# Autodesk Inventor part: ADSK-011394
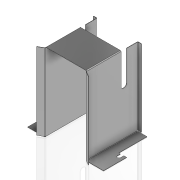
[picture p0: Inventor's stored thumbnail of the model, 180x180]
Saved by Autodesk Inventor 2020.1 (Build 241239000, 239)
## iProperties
Created: 2000-01
Part Number: ADSK-011394
Material: 1.0312 DC05
Document SubType Name: Tôlerie
Designer: glanglot
Density: 1 g/cm^3
Sheet Metal Rule: Stahlblech 1.0312 - DC05 -   1.5mm
Appearance: Chrom - poliert
Mass: 262.367 g
Surface Area: 3543.47 cm^2
Volume: 262.367 cm^3
Sheet Metal Width: 235,19077 mm
Sheet Metal Length: 887,57168 mm
Sheet Metal Area: 208748,66262 mm^2
Flat Pattern Width: 23.5191 cm
Flat Pattern Length: 88.7572 cm
Flat Pattern Area: 2087.49 cm^2
Control State: 0
Checked Out: False
Master: False
Shininess: 0.0
Length Units: 11269
Angle Units: 11279
Time Units: 11290
Mass Units: 11283
Length Display Precision: 5
Angle Display Precision: 5
Compacted: True
CUTLENGTH: 9.47 X 34.82 (330 SI)
MATERIAL DESC: SHEET,S/S, 16 GA
MATERIAL_NUMBER: A084639
G_L: 887,6x235,2 mm
Thickness: 1,50000 mm
Dimensions: 292x301,6x212,6 mm
Mass: 0,262 kg
Semi finished: Stahlblech 1.0312 - DC05 -   1.5mm
DocNumber: ADSK-011394.ipt
Folder: 01 - Themengebiete\Simplification\01 - Packaging machine\
VDS_Category: 3D Komponenten
Density: 0.0
Volumn: 0.0
Area: 0.0
PropertySet Name: Model Information
Author: glanglot
Revision Number: -
Title: Box
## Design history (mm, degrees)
node "Konturlasche1"
  sketch "Sketch1"
    geometry: L1 (0, 0)-(68, 0); L2 (68, 298.5)-(68, 0)
    constraints: 5 end point, 1 horizontal, 1 vertical
    dimensions: "d54" = 68 distance of L1.start L1.end; "d85" = 298.5 distance of L2.start L1.end
node "Lasche1"
sketch "Sketch5"
  geometry: L1 (66, 179.325)-(66, 295.325); L2 (44, 295.325)-(44, 179.325); L3 (66, 295.325)-(44, 295.325); L4 (0, 297.218)-(0, 293.825) reference; L5 (198.268, -0.175)-(0, -0.175) reference; L6 (0, 295.325)-(198.268, 295.325) reference; L7 (0, 295.325)-(0, -0.175) reference; A1 r 11 centre (55, 179.325) between (44, 179.325) and (66, 179.325)
  constraints: 6 end point, 4 point on circle, 2 point on line, 2 tangent, 1 centre point, 1 collinear, 1 parallel, 1 perpendicular
  dimensions: "d19" = 22 distance between parallel lines of L1 L2; "d86" = 116 distance from line of L6 A1.centre; "d87" = 44 distance between parallel lines of L7 L2
feature "Ausklinkung1" sketch "Sketch5" dims "d79" = 1.5 (= Thickness), "d80" = 0
sketch "Skizze12"
  geometry: L1 (0, 0)-(30, 0); L2 (30, 0)-(30, 111); L3 (30, 111)-(0, 111); L4 (0, 111)-(0, 0)
  constraints: 8 end point, 2 parallel, 1 horizontal, 1 perpendicular
  dimensions: "d81" = 30 distance of L3.end L2.end; "d82" = 111 distance of L2.end L1.end
feature "Ausklinkung2" sketch "Skizze12" dims "d83" = 1.5 (= Thickness), "d84" = 0
node "Lasche2"
feature "Ecke4" dims "d56" = 1.5 (= Thickness), "d98" = 6 (= CornerReliefSize), "d99" = 1.5 (= TransitionRadius), "d100" = 1.5 (= TailleJeu), "d101" = 0, "d102" = 10
workplane "Arbeitsebene3"
sketch "Sketch10"
  geometry: L1 (10.75, -76.464)-(10.75, -89.025); L2 (23.25, -76.464)-(23.25, -89.025); L3 (10.75, -89.025)-(23.25, -89.025); L4 (0, -89.025)-(30, -89.025) reference; L5 (63.973, -197.464)-(30, -197.464) reference; L6 (0, -89.025)-(0, -0.025) reference; L7 (146, 54.992)-(146, -242.627) reference; A1 r 6.25 centre (17, -76.464) between (23.25, -76.464) and (10.75, -76.464)
  constraints: 6 end point, 2 point on circle, 2 tangent, 2 vertical, 1 centre point, 1 collinear, 1 horizontal
  dimensions: "d103" = 121 distance from line of A1.centre L5; "d104" = 12.5 distance of L1.end L2.end; "d114" = 129 distance from line of L7 A1.centre
feature "Ausklinkung3" sketch "Sketch10" dims "d106" = 1.5 (= Thickness), "d107" = 0
node "Fillet7" dims "d53" = 3
node "Mirror1"
feature "Biegung4" dims "d56" = 1.5 (= Thickness), "d109" = 1.5 (= BendReliefWidth), "d110" = 0.75 (= BendReliefDepth), "d111" = 3 (= MinimumRemnant), "d112" = 1.5 (= TransitionRadius), "d113" = 1.5 (= BendRadius), "SeamGap" = 0.00508
node "Solide1"
node "Corps solides"
node "Corps surfaciques"
feature "Grobblech1" dims "d56" = 1.5 (= Thickness), "d57" = 1.5 (= BendReliefWidth), "d58" = 0.75 (= BendReliefDepth), "d59" = 3 (= MinimumRemnant), "d60" = 1.5 (= TransitionRadius), "d61" = 200, "d62" = 1.5 (= BendRadius), "d63" = 1.5, "d64" = 6 (= CornerReliefSize), "d65" = 1.5 (= TailleJeu), "d66" = 1.5 (= TailleRayonJacobi), "SeamGap" = 0.00508
node "Volumenkörper2"
feature "Biegung1" dims "d56" = 1.5 (= Thickness), "d57" = 1.5 (= BendReliefWidth), "d58" = 0.75 (= BendReliefDepth), "d59" = 3 (= MinimumRemnant), "d60" = 1.5 (= TransitionRadius), "d62" = 1.5 (= BendRadius), "d63" = 1.5, "SeamGap" = 0.00508
feature "Ecke1" dims "d63" = 1.5, "d64" = 6 (= CornerReliefSize), "d65" = 1.5 (= TailleJeu), "d66" = 1.5 (= TailleRayonJacobi)
sketch "Skizze11"
  geometry: L1 through (-147.75, 0) direction (1, -2.37e-17); L2 through (0, 12.5) direction (1.28e-16, 1); L3 (0, 25)-(-295.5, 25); L4 (-295.5, 25)-(-295.5, 0)
  constraints: 6 end point, 1 horizontal, 1 perpendicular, 1 vertical
feature "Grobblech2" dims "d56" = 1.5 (= Thickness), "d67" = 1.5 (= BendReliefWidth), "d68" = 0.75 (= BendReliefDepth), "d69" = 3 (= MinimumRemnant), "d70" = 1.5 (= TransitionRadius), "d71" = 25, "d72" = 60 deg, "d73" = 1.5 (= BendRadius), "d74" = 6 (= CornerReliefSize), "d75" = 1.5 (= TailleJeu), "d76" = 1.5 (= TailleRayonJacobi), "SeamGap" = 0.00508
feature "Biegung2" dims "d56" = 1.5 (= Thickness), "d67" = 1.5 (= BendReliefWidth), "d68" = 0.75 (= BendReliefDepth), "d69" = 3 (= MinimumRemnant), "d70" = 1.5 (= TransitionRadius), "d71" = 25, "d72" = 60 deg, "d73" = 1.5 (= BendRadius), "SeamGap" = 0.00508
feature "Ecke2" dims "d71" = 25, "d72" = 60 deg, "d74" = 6 (= CornerReliefSize), "d75" = 1.5 (= TailleJeu), "d76" = 1.5 (= TailleRayonJacobi)
sketch "Skizze13"
  geometry: L1 through (0, 147.75) direction (-1.2e-16, -1); L2 through (7, 0) direction (1, -1.19e-16); L3 (14, 0)-(14, 295.5); L4 (14, 295.5)-(0, 295.5)
  constraints: 6 end point, 1 horizontal, 1 perpendicular, 1 vertical
feature "Grobblech3" dims "d56" = 1.5 (= Thickness), "d88" = 1.5 (= BendReliefWidth), "d89" = 0.75 (= BendReliefDepth), "d90" = 3 (= MinimumRemnant), "d91" = 1.5 (= TransitionRadius), "d92" = 14, "d93" = 90 deg, "d94" = 1.5 (= BendRadius), "d95" = 6 (= CornerReliefSize), "d96" = 1.5 (= TailleJeu), "d97" = 1.5 (= TailleRayonJacobi), "SeamGap" = 0.00508
feature "Biegung3" dims "d56" = 1.5 (= Thickness), "d88" = 1.5 (= BendReliefWidth), "d89" = 0.75 (= BendReliefDepth), "d90" = 3 (= MinimumRemnant), "d91" = 1.5 (= TransitionRadius), "d92" = 14, "d93" = 90 deg, "d94" = 1.5 (= BendRadius), "SeamGap" = 0.00508
feature "Ecke3" dims "d92" = 14, "d93" = 90 deg, "d95" = 6 (= CornerReliefSize), "d96" = 1.5 (= TailleJeu), "d97" = 1.5 (= TailleRayonJacobi)
feature "Definition1"
other parameters: "d15" = 25.4, "Thickness" = 1.5 (derived), "BendRadius" = 1.5 (= Thickness), "BendReliefWidth" = 1.5 (= Thickness), "BendReliefDepth" = 0.75 (= 0.5 x Thickness), "CornerReliefSize" = 6 (= 4 x Thickness), "MinimumRemnant" = 3 (= 2 x Thickness), "TransitionRadius" = 1.5 (= BendRadius), "TailleRayonJacobi" = 1.5 (= BendRadius), "TailleJeu" = 1.5 (= Thickness), "d108" = 78, "BendRadius" = 1.5, "BendReliefDepth" = 0.75, "BendReliefWidth" = 1.5, "CornerReliefSize" = 6, "MinimumRemnant" = 3, "TailleJeu" = 1.5, "TailleRayonJacobi" = 1.5, "Thickness" = 1.5, "TransitionRadius" = 1.5
